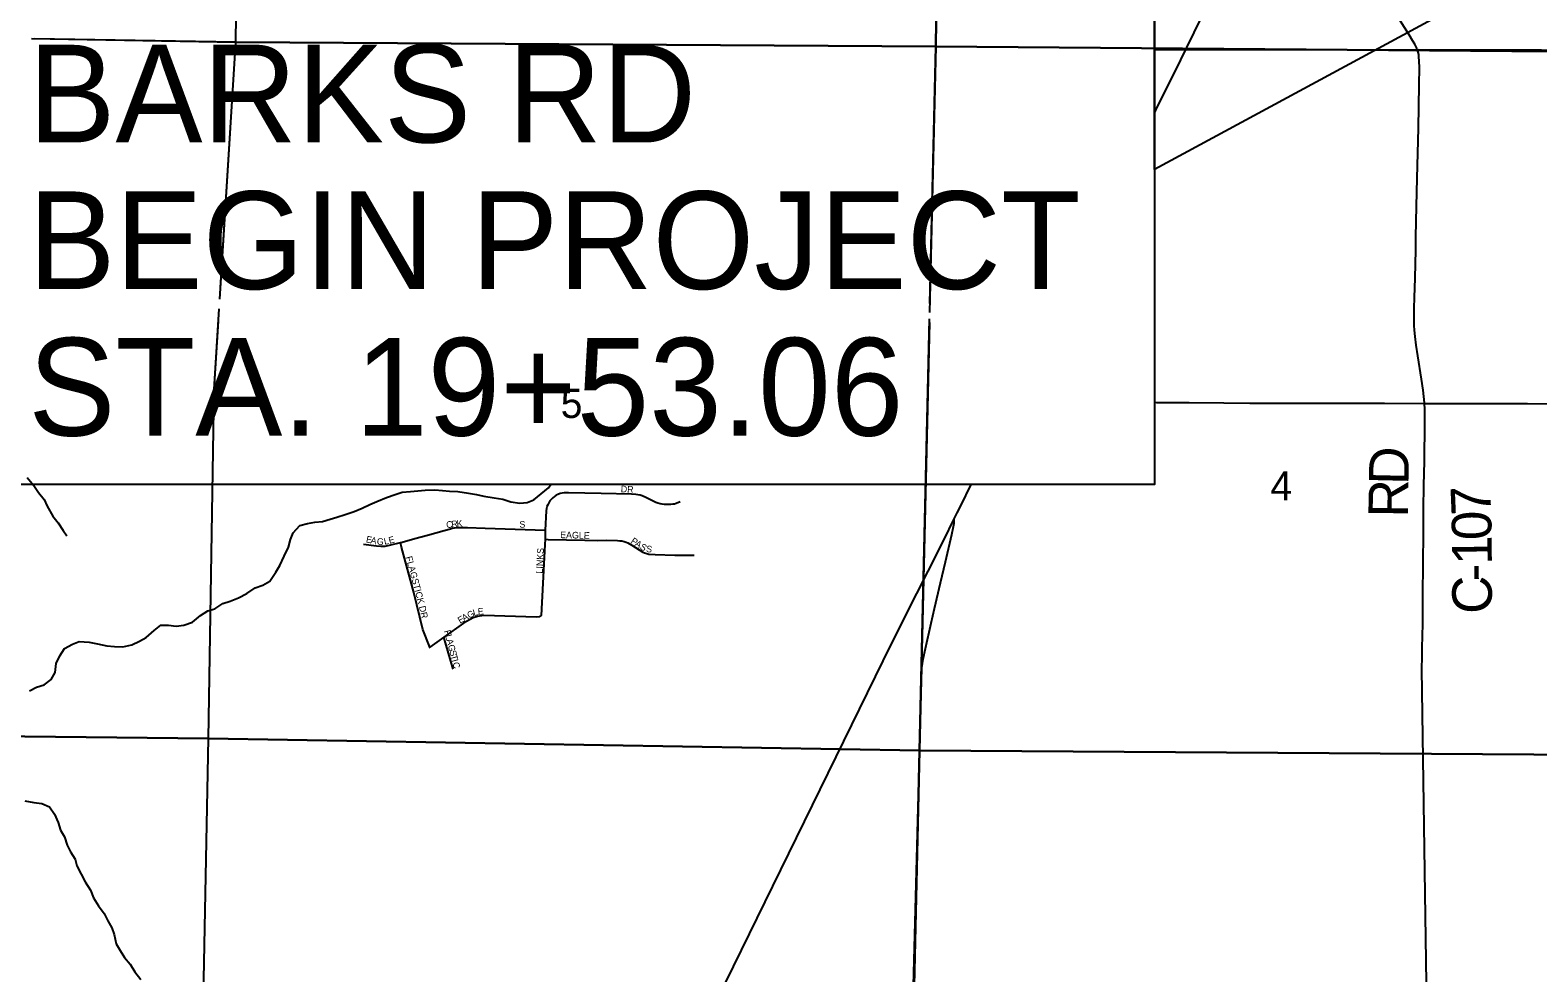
# Model space of a CAD drawing. Extents: x -9.1 to 34, y -3.1 to 22.
# Drawn here: x 2.915 to 5.075, y 16.445 to 17.795 of the extents above; entities that cross this region are included whole.
import ezdxf

# ---------------------------------------------------------------- set-up
doc = ezdxf.new("R2010")
doc.units = 0
for name, color, linetype in [('GM_X_County_Road', 7, 'Continuous'), ('GM_X_County_Road_Text', 7, 'Continuous'), ('GM_X_Minor_River', 7, 'Continuous'), ('GM_X_Section', 7, 'Continuous'), ('GM_X_Section_Text', 7, 'Continuous'), ('GM_X_State_Route', 7, 'Continuous'), ('GM_X_Township', 7, 'Continuous'), ('GM_X_Township_Subdivision', 7, 'Continuous'), ('GM_X_Township_Subdivision_Text', 7, 'Continuous'), ('SH_Text', 7, 'Continuous')]:
    doc.layers.add(name, color=color, linetype=linetype)

msp = doc.modelspace()

# ---------------------------------------------------------------- linework, layer by layer
at = {"layer": 'GM_X_County_Road'}
for points in [[(4.9021, 17.7686), (4.9018, 17.7695), (4.9004, 17.7724), (4.899, 17.7752), (4.8959, 17.7806), (4.8909, 17.7885), (4.8809, 17.8043), (4.8678, 17.8254), (4.8529, 17.8491), (4.8331, 17.8806), (4.8085, 17.9202), (4.782, 17.9623), (4.7622, 17.9939), (4.7459, 18.0203), (4.7361, 18.0362), (4.7161, 18.0665), (4.7133, 18.0707)], [(4.9129, 17.2606), (4.9128, 17.2615), (4.912, 17.2708), (4.9109, 17.2798), (4.9086, 17.2953), (4.9032, 17.329), (4.901, 17.3443), (4.8996, 17.3566), (4.8986, 17.3658), (4.8982, 17.3722), (4.8983, 17.3843), (4.8983, 17.3969), (4.8988, 17.4123), (4.8995, 17.4403), (4.9003, 17.4807), (4.9006, 17.4994), (4.9015, 17.5429), (4.9026, 17.5832), (4.9041, 17.6547), (4.9052, 17.7168), (4.9056, 17.7417), (4.9055, 17.7511), (4.905, 17.7573), (4.9046, 17.7605), (4.9039, 17.7636), (4.9029, 17.7666), (4.9021, 17.7686)], [(4.5258, 17.2623), (4.529, 17.2622), (4.5757, 17.262), (4.6254, 17.2615), (4.6627, 17.261), (4.6937, 17.2608), (4.7186, 17.261), (4.7466, 17.261), (4.7963, 17.261), (4.8554, 17.2612), (4.9113, 17.2606), (4.9129, 17.2606)], [(4.9092, 16.8801), (4.9095, 16.8981), (4.9098, 16.9106), (4.9107, 16.9447), (4.9107, 16.9603), (4.9107, 16.9758), (4.9106, 16.9882), (4.9106, 16.9975), (4.9109, 17.0193), (4.9111, 17.0348), (4.9112, 17.0379), (4.9112, 17.041), (4.9114, 17.0658), (4.9115, 17.0752), (4.9115, 17.0814), (4.9115, 17.0844), (4.9115, 17.0875), (4.9116, 17.0906), (4.9117, 17.1093), (4.9121, 17.1434), (4.9128, 17.1776), (4.9131, 17.1962), (4.9134, 17.2148), (4.9136, 17.2242), (4.9136, 17.2366), (4.9133, 17.2522), (4.9129, 17.2606)], [(4.9129, 17.2606), (4.9486, 17.2605), (4.9921, 17.2607), (5.0605, 17.2607), (5.0946, 17.2602)], [(4.18, 16.4081), (4.1925, 16.882), (4.1946, 16.8943), (4.1977, 16.9095), (4.206, 16.9459), (4.2107, 16.9671), (4.2192, 17.0035), (4.2265, 17.0337), (4.2354, 17.0731), (4.2381, 17.0844), (4.2385, 17.0869), (4.2388, 17.0887), (4.2389, 17.0911), (4.239, 17.0951)], [(4.9149, 16.2544), (4.9149, 16.2579), (4.9148, 16.2802), (4.9158, 16.3392), (4.9165, 16.3982), (4.9092, 16.8801)]]:
    msp.add_lwpolyline(points, dxfattribs=at)
at = {"layer": 'GM_X_Minor_River'}
for points in [[(2.9106, 17.1544), (2.9199, 17.1432), (2.9265, 17.1332), (2.9347, 17.1232), (2.9391, 17.1137), (2.9471, 17.0991), (2.9549, 17.0895), (2.9619, 17.0788), (2.9671, 17.0711)], [(2.9135, 16.8488), (2.9238, 16.8543), (2.9348, 16.8575), (2.9448, 16.8653), (2.9503, 16.8754), (2.952, 16.8883), (2.9574, 16.8992), (2.9637, 16.9097), (2.9755, 16.9159), (2.985, 16.9196), (2.999, 16.9186), (3.0114, 16.9161), (3.0246, 16.9132), (3.0356, 16.9126), (3.0476, 16.912), (3.0602, 16.9149), (3.0712, 16.92), (3.0811, 16.9255), (3.0923, 16.9355), (3.1018, 16.9429), (3.1128, 16.9431), (3.1241, 16.9418), (3.1347, 16.9431), (3.1473, 16.9471), (3.1588, 16.9571), (3.1691, 16.9634), (3.1793, 16.9666), (3.1908, 16.974), (3.2015, 16.9776), (3.2132, 16.982), (3.2251, 16.9886), (3.2369, 16.9963), (3.248, 17.0003), (3.2579, 17.0062), (3.2668, 17.019), (3.2726, 17.0287), (3.2785, 17.0419), (3.2848, 17.0547), (3.2876, 17.0656), (3.2915, 17.0754), (3.3012, 17.0858), (3.3122, 17.0887), (3.3224, 17.0904), (3.3338, 17.0917), (3.3448, 17.095), (3.3543, 17.0978), (3.3661, 17.1014), (3.379, 17.1057), (3.3904, 17.1108), (3.4015, 17.116), (3.4117, 17.1203), (3.4254, 17.1258), (3.4376, 17.1301), (3.4479, 17.1337), (3.4596, 17.1347), (3.4808, 17.1366), (3.4948, 17.1367), (3.5058, 17.1358), (3.5156, 17.1352), (3.5277, 17.1343), (3.5428, 17.1321), (3.5544, 17.13), (3.565, 17.1279), (3.5797, 17.1254), (3.5921, 17.1233), (3.6034, 17.1197), (3.6162, 17.1179), (3.6268, 17.1185), (3.6367, 17.1225), (3.6574, 17.1396), (3.661, 17.1445)], [(2.9068, 16.6916), (2.9199, 16.6891), (2.9313, 16.6877), (2.9422, 16.683), (2.9495, 16.6722), (2.9546, 16.6604), (2.9582, 16.6493), (2.9641, 16.6398), (2.9677, 16.628), (2.9725, 16.6184), (2.9791, 16.6077), (2.9816, 16.5982), (2.9878, 16.5863), (2.9937, 16.5752), (3.001, 16.5633), (3.0054, 16.5523), (3.0124, 16.5408), (3.0209, 16.53), (3.026, 16.5193), (3.0319, 16.5097), (3.0351, 16.4998), (3.038, 16.4865), (3.0438, 16.4769), (3.0497, 16.467), (3.0579, 16.4573), (3.0649, 16.4466), (3.0734, 16.4355)]]:
    msp.add_lwpolyline(points, dxfattribs=at)
at = {"layer": 'GM_X_Section'}
for points in [[(2.9168, 17.7832), (3.2094, 17.7781), (3.222, 18.7858), (2.6, 18.7961)], [(3.1864, 17.4099), (3.2094, 17.7781), (2.9211, 17.7831)], [(3.1874, 17.4265), (3.2094, 17.7781), (4.2125, 17.7717), (4.2036, 17.391)], [(4.2039, 17.4039), (4.2125, 17.7717), (5.2149, 17.764), (5.2164, 16.757), (4.189, 16.7633), (4.2034, 17.3818)], [(2.6, 16.7869), (3.1704, 16.7805), (3.1783, 17.2806), (3.1855, 17.3961)], [(4.2033, 17.3765), (4.189, 16.7633), (3.1704, 16.7805), (3.1783, 17.2806), (3.1845, 17.3787)], [(2.6, 15.7826), (3.1506, 15.7703), (3.1704, 16.7805), (2.6, 16.7869)]]:
    msp.add_lwpolyline(points, dxfattribs=at)
for points in [[(3.222, 18.7858), (4.2254, 18.771), (4.2125, 17.7717), (3.2094, 17.7781)], [(4.2254, 18.771), (5.2207, 18.771), (5.2149, 17.764), (4.2125, 17.7717)], [(3.1704, 16.7805), (4.189, 16.7633), (4.1665, 15.7524), (3.1506, 15.7703)], [(4.189, 16.7633), (5.2164, 16.757), (5.2057, 15.7528), (4.1665, 15.7524)]]:
    msp.add_lwpolyline(points, close=True, dxfattribs=at)
at = {"layer": 'GM_X_State_Route'}
for points in [[(4.5258, 17.6765), (4.5278, 17.6806), (4.5635, 17.753), (4.5722, 17.7705), (4.5828, 17.7919), (4.6085, 17.8451), (4.635, 17.9013), (4.6637, 17.9633), (4.6821, 18.0027), (4.708, 18.0591), (4.7133, 18.0707), (4.7417, 18.1325), (4.7596, 18.1704)], [(4.2483, 17.1139), (4.2633, 17.1445)], [(3.9003, 16.4081), (4.1488, 16.9151), (4.1855, 16.9883), (4.2017, 17.0206), (4.2242, 17.0649), (4.239, 17.0951), (4.2434, 17.104), (4.2483, 17.1139)]]:
    msp.add_lwpolyline(points, dxfattribs=at)
at = {"layer": 'GM_X_Township'}
msp.add_lwpolyline([(6.2213, 17.7623), (5.9624, 17.7643), (4.9043, 17.7669), (4.571, 17.7666), (4.5258, 17.7669)], dxfattribs=at)
at = {"layer": 'GM_X_Township_Subdivision'}
for points in [[(3.8461, 17.1197), (3.8406, 17.1173), (3.8381, 17.1165), (3.8356, 17.1162), (3.8326, 17.1159), (3.83, 17.1158), (3.8269, 17.1159), (3.8237, 17.1161), (3.8206, 17.1165), (3.8174, 17.117), (3.8143, 17.1177), (3.8113, 17.1188), (3.8055, 17.1214), (3.7972, 17.1257), (3.7916, 17.1282), (3.7887, 17.1291), (3.7857, 17.1298), (3.7827, 17.1303), (3.7765, 17.1307), (3.7329, 17.1314), (3.6861, 17.1327), (3.6799, 17.1325), (3.6769, 17.1321), (3.674, 17.1314), (3.6711, 17.1303), (3.6684, 17.129), (3.6659, 17.1273), (3.6636, 17.1254), (3.6615, 17.1232), (3.6596, 17.1209), (3.6579, 17.1183), (3.6564, 17.1156), (3.6553, 17.1129), (3.6546, 17.11), (3.6542, 17.1069), (3.6527, 17.0791)], [(3.4453, 17.0614), (3.4477, 17.0621), (3.4658, 17.0671), (3.484, 17.072)], [(3.484, 17.072), (3.5079, 17.0784), (3.5169, 17.081), (3.5196, 17.0818), (3.523, 17.0824), (3.526, 17.0828), (3.5289, 17.083), (3.5314, 17.0829), (3.5416, 17.0827), (3.5666, 17.0818), (3.6527, 17.0791)], [(3.6527, 17.0791), (3.6527, 17.0714), (3.6525, 17.066)], [(3.3925, 17.0589), (3.4111, 17.0565), (3.4173, 17.056), (3.4204, 17.056), (3.4235, 17.0563), (3.4296, 17.0574), (3.4453, 17.0614)], [(3.4873, 16.9115), (3.4873, 16.9116), (3.4776, 16.9366), (3.4643, 16.99), (3.4595, 17.0077), (3.447, 17.0549), (3.4453, 17.0614)], [(3.6525, 17.066), (3.6522, 17.0588), (3.6469, 16.9569), (3.6443, 16.9549), (3.6405, 16.9547), (3.5647, 16.9569), (3.5556, 16.9556), (3.5494, 16.9537), (3.5359, 16.9457), (3.5077, 16.9259)], [(3.6525, 17.066), (3.6571, 17.0659), (3.7098, 17.0649), (3.7284, 17.0645), (3.7408, 17.0646), (3.7564, 17.0642), (3.7595, 17.064), (3.7627, 17.0636), (3.7658, 17.063), (3.7688, 17.062), (3.7713, 17.0609), (3.7767, 17.0576), (3.7926, 17.0478), (3.7953, 17.0464), (3.7983, 17.0455), (3.8013, 17.0449), (3.8106, 17.0441), (3.8385, 17.0432), (3.8571, 17.0431), (3.8602, 17.0431), (3.8662, 17.0433)], [(3.5077, 16.9259), (3.4873, 16.9115)], [(3.5209, 16.8801), (3.5077, 16.9259)], [(3.4873, 16.9115), (3.4858, 16.9104)]]:
    msp.add_lwpolyline(points, dxfattribs=at)
at = {"layer": 'SH_Text'}
for points in [[(4.5258, 17.8317), (5.7611, 18.2634), (4.5258, 17.5957)], [(2.873, 17.8317), (4.5258, 17.8317), (4.5258, 17.1445), (2.873, 17.1445)]]:
    msp.add_lwpolyline(points, close=True, dxfattribs=at)

# ---------------------------------------------------------------- texts
at = {"layer": 'GM_X_County_Road_Text'}
for s, rotation, p in [('D', 88.6885, (4.8898, 17.1435)), ('R', 89.395, (4.8893, 17.097)), ('7', 92.3639, (5.0086, 17.1017)), ('0', 91.0325, (5.0092, 17.0653)), ('1', 90.4074, (5.0095, 17.0296)), ('-', 90.1079, (5.0095, 17.006)), ('C', 90.0117, (5.0095, 16.9592))]:
    msp.add_text(s, height=0.0568, rotation=rotation, dxfattribs=at).set_placement(p)
at = {"layer": 'GM_X_Section_Text'}
for s, p in [('5', (3.675, 17.2398)), ('4', (4.6921, 17.1217))]:
    msp.add_text(s, height=0.0419, rotation=0, dxfattribs=at).set_placement(p)
at = {"layer": 'GM_X_Township_Subdivision_Text'}
for s, rotation, p in [('DR', 356.989, (3.7609, 17.1335)), ('C', 7.0347, (3.5115, 17.0819)), ('R', 7.0106, (3.5189, 17.0828)), ('K', 4.4624, (3.5262, 17.0837)), ('S', 0, (3.6158, 17.0827)), ('E', 348.2774, (3.3954, 17.0618)), ('E', 15.0648, (3.4297, 17.0595)), ('EAGLE', 358.7554, (3.6742, 17.0677)), ('A', 348.3022, (3.4019, 17.0605)), ('G', 354.0561, (3.4111, 17.0586)), ('L', 12.5402, (3.4227, 17.058)), ('LINKS', 87.2035, (3.6491, 17.0168)), ('P', 325.3325, (3.7745, 17.0615)), ('A', 327.5811, (3.7803, 17.0574)), ('S', 328.9707, (3.7876, 17.0528)), ('S', 350.352, (3.7969, 17.0481)), ('FLAGSTICK', 285.1226, (3.4526, 17.0405)), ('DR', 282.5327, (3.4718, 16.9696)), ('G', 26.8485, (3.5437, 16.9522)), ('L', 16.6208, (3.5507, 16.9558)), ('E', 5.4714, (3.5566, 16.9577)), ('E', 29.45, (3.5307, 16.9449)), ('A', 29.4304, (3.5365, 16.9482)), ('F', 284.891, (3.5076, 16.9347)), ('L', 284.888, (3.5093, 16.9283)), ('A', 284.9004, (3.511, 16.9219)), ('G', 284.8737, (3.5131, 16.9138)), ('S', 284.9126, (3.5153, 16.9057)), ('T', 284.891, (3.517, 16.8993)), ('I', 284.8738, (3.5187, 16.8929)), ('C', 284.9033, (3.5198, 16.8888))]:
    msp.add_text(s, height=0.00947, rotation=rotation, dxfattribs=at).set_placement(p)
at = {"layer": 'SH_Text'}
for s, p in [('BARKS RD', (2.912, 17.6345)), ('BEGIN PROJECT', (2.912, 17.4245)), ('STA. 19+53.06', (2.912, 17.2145))]:
    msp.add_text(s, height=0.14, dxfattribs=at).set_placement(p)

doc.saveas('drawing.dxf')
